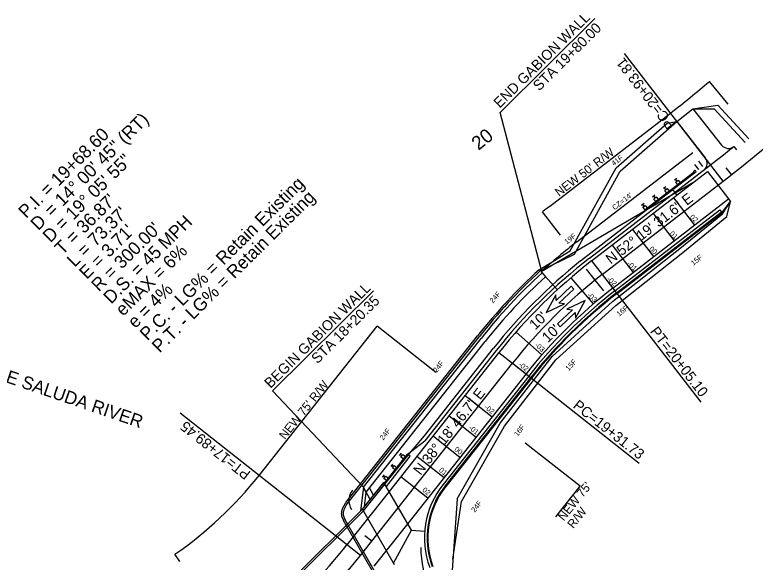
# Model space of a CAD drawing. Extents: x 126 to 1541327, y 13613 to 1200627.
# Drawn here: x 1539946.5 to 1540376.1, y 1199486.8 to 1199804.6 of the extents above; entities that cross this region are included whole.
import ezdxf

# ---------------------------------------------------------------- set-up
doc = ezdxf.new("R2010")
doc.units = 0
for name, color, linetype in [('BR_CONCRETE', 7, 'Continuous'), ('BR_PROPOSED_TRAVELWAY', 7, 'Continuous'), ('RD_HC_Cl', 7, 'Continuous'), ('RD_HC_Data', 7, 'Continuous'), ('RD_HC_Data_Tic', 7, 'Continuous'), ('RD_HC_TX_Sta50', 7, 'Continuous'), ('RD_PD_ALT1_TX', 7, 'Continuous'), ('RD_PD_BOC', 7, 'Continuous'), ('RD_PD_CstnLmt', 7, 'Continuous'), ('RD_PD_CstnLmt_TX', 7, 'Continuous'), ('RD_PD_DR_ErosCtrl', 7, 'Continuous'), ('RD_PD_Driveway', 7, 'Continuous'), ('RD_PD_EOP', 7, 'Continuous'), ('RD_PD_Final_TrvlWay', 7, 'Continuous'), ('RD_PD_Final_TX', 7, 'Continuous'), ('RD_PD_FOC', 7, 'Continuous'), ('RD_PD_GR', 7, 'Continuous'), ('RD_PD_PaveShd', 7, 'Continuous'), ('RD_PD_RW', 7, 'Continuous'), ('RD_PD_WallFill', 7, 'Continuous'), ('RD_Sketch1', 7, 'Continuous'), ('RD_Sketch8', 7, 'Continuous')]:
    doc.layers.add(name, color=color, linetype=linetype)

# ---------------------------------------------------------------- blocks, each defined once
blk = doc.blocks.new('Guardrail_MTBBC2_Transition')
at = {"layer": 'RD_PD_GR'}
for p, q in [((0, 0.5), (0, 0)), ((21.25, 0.5), (0, 0.5)), ((0, 0), (21.25, 0)), ((3.875, 3.75), (2.125, 3.75)), ((2.125, 0.5), (2.125, 2.5)), ((2.125, 2.5), (3.875, 2.5)), ((3.875, 0.5), (2.125, 0.5)), ((3, 2.5), (3, 3.75)), ((3.875, 2.5), (3.875, 0.5)), ((11.875, 3.75), (10.125, 3.75)), ((10.125, 0.5), (10.125, 2.5)), ((10.125, 2.5), (11.875, 2.5)), ((11.875, 0.5), (10.125, 0.5)), ((11, 2.5), (11, 3.75)), ((11.875, 2.5), (11.875, 0.5)), ((15, 0.5), (15, 0)), ((19.875, 3.75), (18.125, 3.75)), ((18.125, 0.5), (18.125, 2.5)), ((18.125, 2.5), (19.875, 2.5)), ((19.875, 0.5), (18.125, 0.5)), ((19, 2.5), (19, 3.75)), ((19.875, 2.5), (19.875, 0.5)), ((21.25, 0), (21.25, 0.5))]:
    blk.add_line(p, q, dxfattribs=at)
blk = doc.blocks.new('Guardrail_MT2_Leading_with_Buffer')
at = {"layer": 'RD_PD_GR'}
for p, q in [((17.52, 4.7), (15.77, 4.61)), ((16.72, 3.41), (16.65, 4.66)), ((25.51, 5.13), (23.76, 5.04)), ((24.7, 3.84), (24.64, 5.09)), ((38.94, 2.11), (38.74, 5.85)), ((41.94, 2.27), (41.74, 6.01)), ((1.55, 3.84), (-0.2, 3.74)), ((-0.13, 2.5), (1.61, 2.59)), ((-0.03, 0.5), (-0.13, 2.5)), ((35.92, 2.44), (-0.03, 0.5)), ((1.72, 0.59), (-0.03, 0.5)), ((-0.03, 0.5), (0, 0)), ((0, 0), (36.95, 2)), ((0.74, 2.54), (0.67, 3.79)), ((1.61, 2.59), (1.72, 0.59)), ((9.53, 4.27), (7.79, 4.18)), ((7.85, 2.93), (9.6, 3.02)), ((7.96, 0.93), (7.85, 2.93)), ((9.71, 1.03), (7.96, 0.93)), ((8.73, 2.98), (8.66, 4.22)), ((9.6, 3.02), (9.71, 1.03)), ((15.84, 3.36), (17.59, 3.45)), ((15.95, 1.36), (15.84, 3.36)), ((17.7, 1.46), (15.95, 1.36)), ((17.59, 3.45), (17.7, 1.46)), ((20.17, -2.67), (19.97, 1.08)), ((23.83, 3.79), (25.58, 3.89)), ((23.94, 1.79), (23.83, 3.79)), ((25.69, 1.89), (23.94, 1.79)), ((25.58, 3.89), (25.69, 1.89)), ((32.43, 2.25), (32.45, 1.75)), ((36.89, 3), (35.89, 2.94)), ((35.89, 2.94), (35.92, 2.44)), ((36.95, 2), (36.89, 3))]:
    blk.add_line(p, q, dxfattribs=at)

msp = doc.modelspace()

# ---------------------------------------------------------------- linework, layer by layer
at = {"layer": 'BR_CONCRETE'}
for p, q in [((1540148.8, 1199530.38), (1540147.11, 1199516.61)), ((1540148.21, 1199517.71), (1540160.73, 1199533.19)), ((1540148.25, 1199517.64), (1540160.77, 1199533.12)), ((1540148.77, 1199516.74), (1540160.63, 1199531.35)), ((1540150.28, 1199527.59), (1540148.8, 1199530.38)), ((1540160.63, 1199531.35), (1540161.17, 1199532.42)), ((1540176.63, 1199505.52), (1540160.73, 1199533.19)), ((1540150.28, 1199527.59), (1540149.22, 1199518.96)), ((1540077.64, 1199447.44), (1540148.21, 1199517.71)), ((1540077.68, 1199447.36), (1540148.25, 1199517.64)), ((1540078.2, 1199446.47), (1540148.77, 1199516.74)), ((1540166.77, 1199485.39), (1540148.21, 1199517.71)), ((1540166.22, 1199486.37), (1540176.63, 1199505.52))]:
    msp.add_line(p, q, dxfattribs=at)
at = {"layer": 'BR_PROPOSED_TRAVELWAY'}
for p, q in [((1540163.75, 1199527.93), (1540139.23, 1199496.89)), ((1540174.48, 1199509.25), (1540154.92, 1199484.5))]:
    msp.add_line(p, q, dxfattribs=at)
msp.add_arc((1539911.68, 1199676.68), 290, 301.8034, 321.687, dxfattribs=at)
at = {"layer": 'RD_HC_Cl'}
for p, q in [((1540287.32, 1199653.79), (1540357.53, 1199708.01)), ((1540147.08, 1199490.69), (1540235.28, 1199602.33))]:
    msp.add_line(p, q, dxfattribs=at)
for centre, radius, start, end in [((1539929.71, 1200262.06), 700, 307.67455, 318.32753), ((1540470.67, 1199416.35), 300, 127.6745, 141.687), ((1539911.68, 1199676.68), 300, 272.8619, 321.687)]:
    msp.add_arc(centre, radius, start, end, dxfattribs=at)
at = {"layer": 'RD_HC_Data'}
for p, q in [((1540357.53, 1199708.01), (1540300.32, 1199782.11)), ((1540287.32, 1199653.79), (1540344.54, 1199579.69)), ((1540235.28, 1199602.33), (1540308.74, 1199544.29)), ((1540147.08, 1199490.69), (1540042.49, 1199573.33))]:
    msp.add_line(p, q, dxfattribs=at)
at = {"layer": 'RD_HC_Data_Tic'}
for p, q in [((1540362.42, 1199711.82), (1540359.33, 1199715.75)), ((1540283.31, 1199650.65), (1540278.32, 1199656.89)), ((1540288.31, 1199644.4), (1540283.31, 1199650.65)), ((1540215.61, 1199577.44), (1540211.69, 1199580.54)), ((1540153.62, 1199498.98), (1540149.69, 1199502.08))]:
    msp.add_line(p, q, dxfattribs=at)
at = {"layer": 'RD_PD_ALT1_TX'}
for p, q in [((1540328.7, 1199698.38), (1540340.92, 1199682.55)), ((1540316.83, 1199689.21), (1540329.05, 1199673.38)), ((1540304.95, 1199680.05), (1540317.18, 1199664.22)), ((1540293.08, 1199670.88), (1540305.31, 1199655.05)), ((1540281.21, 1199661.71), (1540293.43, 1199645.88)), ((1540269.18, 1199651.93), (1540282.18, 1199636.73)), ((1540237.35, 1199620.45), (1540252.4, 1199607.28)), ((1540227.44, 1199608.53), (1540243.13, 1199596.13)), ((1540207.77, 1199583.64), (1540223.46, 1199571.24)), ((1540198.47, 1199571.87), (1540214.16, 1199559.47)), ((1540189.17, 1199560.1), (1540204.86, 1199547.7)), ((1540179.87, 1199548.33), (1540195.56, 1199535.93)), ((1540170.57, 1199536.56), (1540186.26, 1199524.16))]:
    msp.add_line(p, q, dxfattribs=at)
at = {"layer": 'RD_PD_BOC'}
for p, q in [((1540295.88, 1199642.71), (1540356.75, 1199689.72)), ((1540355.52, 1199691.3), (1540356.75, 1199689.72)), ((1540246.27, 1199593.65), (1540196.54, 1199530.72)), ((1540161.03, 1199532.67), (1540174.44, 1199549.64))]:
    msp.add_line(p, q, dxfattribs=at)
for centre, radius, start, end in [((1540470.67, 1199416.35), 286, 127.6745, 141.687), ((1540234.21, 1199500.96), 48, 141.687, 200.1561)]:
    msp.add_arc(centre, radius, start, end, dxfattribs=at)
at = {"layer": 'RD_PD_CstnLmt'}
for p, q in [((1540339.99, 1199750.04), (1540352.24, 1199750.03)), ((1540352.24, 1199750.03), (1540370.26, 1199730.47)), ((1540297.73, 1199713.78), (1540330.56, 1199742.62)), ((1540271.25, 1199665.73), (1540297.73, 1199713.78)), ((1540357.17, 1199689.15), (1540361.86, 1199696.19)), ((1540332.34, 1199668.96), (1540357.17, 1199689.15)), ((1540293.35, 1199638.1), (1540332.34, 1199668.96)), ((1540251.41, 1199655.9), (1540271.25, 1199665.73)), ((1540258.24, 1199606.31), (1540293.35, 1199638.1)), ((1540139.32, 1199520.8), (1540215.86, 1199617.68)), ((1540228.23, 1199567.47), (1540258.24, 1199606.31)), ((1540203.17, 1199523.55), (1540228.23, 1199567.47)), ((1540203.17, 1199523.55), (1540198.31, 1199453.66)), ((1540158.58, 1199475.93), (1540138.18, 1199511.5))]:
    msp.add_line(p, q, dxfattribs=at)
msp.add_arc((1540470.67, 1199416.35), 324.75, 132.4676, 141.687, dxfattribs=at)
msp.add_spline([(1540139.32, 1199520.8), (1540138.72, 1199519.85), (1540138.14, 1199518.8), (1540137.42, 1199517.27), (1540137.04, 1199515.8), (1540136.98, 1199514.76), (1540137.15, 1199513.68), (1540138.18, 1199511.5)], degree=3, dxfattribs=at)
at = {"layer": 'RD_PD_DR_ErosCtrl'}
for p, q in [((1540339.99, 1199750.04), (1540354.45, 1199752.06)), ((1540354.45, 1199752.06), (1540372.47, 1199732.51)), ((1540295.36, 1199715.69), (1540325.01, 1199741.74)), ((1540320.46, 1199739.93), (1540320.46, 1199739.93)), ((1540325.01, 1199741.74), (1540330.56, 1199742.62)), ((1540325.01, 1199741.74), (1540325.01, 1199741.74)), ((1540268.82, 1199667.55), (1540295.36, 1199715.69)), ((1540359.67, 1199687.49), (1540361.86, 1199696.19)), ((1540334.2, 1199666.61), (1540359.67, 1199687.49)), ((1540250.74, 1199656.64), (1540268.82, 1199667.55)), ((1540295.29, 1199635.81), (1540334.2, 1199666.61)), ((1540260.45, 1199604.26), (1540295.29, 1199635.81)), ((1540138.53, 1199521.42), (1540215.08, 1199618.3)), ((1540230.74, 1199565.8), (1540260.45, 1199604.26)), ((1540205.77, 1199522.06), (1540230.74, 1199565.8)), ((1540200.74, 1199488.6), (1540205.77, 1199522.06)), ((1540157.72, 1199475.43), (1540137.31, 1199511))]:
    msp.add_line(p, q, dxfattribs=at)
for centre, radius, start, end in [((1540470.67, 1199416.35), 325.75, 132.4676, 141.687), ((1540150.09, 1199522.59), 9.74, 141.434, 211.687)]:
    msp.add_arc(centre, radius, start, end, dxfattribs=at)
msp.add_open_spline([(1540138.49, 1199521.36), (1540138.36, 1199521.17), (1540138.24, 1199520.99), (1540138.07, 1199520.71), (1540138.01, 1199520.62), (1540137.93, 1199520.48), (1540137.9, 1199520.44), (1540137.87, 1199520.39), (1540137.87, 1199520.38), (1540137.86, 1199520.38), (1540137.86, 1199520.38), (1540137.86, 1199520.38), (1540137.86, 1199520.38), (1540137.86, 1199520.38), (1540137.86, 1199520.38), (1540137.86, 1199520.37), (1540137.85, 1199520.35), (1540137.83, 1199520.33), (1540137.81, 1199520.29), (1540137.8, 1199520.27), (1540137.72, 1199520.14), (1540137.67, 1199520.04), (1540137.56, 1199519.84), (1540137.5, 1199519.75), (1540137.4, 1199519.55), (1540137.35, 1199519.46), (1540137.29, 1199519.34), (1540137.28, 1199519.32), (1540137.26, 1199519.29), (1540137.26, 1199519.28), (1540137.25, 1199519.26), (1540137.25, 1199519.26), (1540137.25, 1199519.26), (1540137.25, 1199519.26), (1540137.25, 1199519.26), (1540137.25, 1199519.25), (1540137.24, 1199519.24), (1540137.21, 1199519.18), (1540137.18, 1199519.13), (1540137.05, 1199518.88), (1540136.96, 1199518.68), (1540136.77, 1199518.28), (1540136.68, 1199518.08), (1540136.57, 1199517.83), (1540136.55, 1199517.77), (1540136.52, 1199517.71), (1540136.51, 1199517.69), (1540136.51, 1199517.67), (1540136.5, 1199517.66), (1540136.5, 1199517.65), (1540136.5, 1199517.65), (1540136.5, 1199517.65), (1540136.5, 1199517.65), (1540136.5, 1199517.65), (1540136.5, 1199517.65), (1540136.48, 1199517.62), (1540136.47, 1199517.59), (1540136.41, 1199517.44), (1540136.37, 1199517.32), (1540136.29, 1199517.08), (1540136.26, 1199516.96), (1540136.2, 1199516.72), (1540136.17, 1199516.61), (1540136.12, 1199516.38), (1540136.1, 1199516.26), (1540136.07, 1199516.09), (1540136.06, 1199516.04), (1540136.05, 1199515.98), (1540136.05, 1199515.97), (1540136.05, 1199515.97), (1540136.05, 1199515.96), (1540136.05, 1199515.96), (1540136.05, 1199515.96), (1540136.05, 1199515.96), (1540136.05, 1199515.95), (1540136.04, 1199515.93), (1540136.04, 1199515.9), (1540136.03, 1199515.85), (1540136.03, 1199515.82), (1540136.01, 1199515.66), (1540136, 1199515.53), (1540135.98, 1199515.28), (1540135.98, 1199515.15), (1540135.98, 1199514.97), (1540135.98, 1199514.91), (1540135.98, 1199514.82), (1540135.98, 1199514.79), (1540135.98, 1199514.76), (1540135.98, 1199514.75), (1540135.98, 1199514.73), (1540135.98, 1199514.73), (1540135.98, 1199514.73), (1540135.98, 1199514.73), (1540135.98, 1199514.72), (1540135.98, 1199514.72), (1540135.98, 1199514.71), (1540135.98, 1199514.69), (1540135.99, 1199514.62), (1540135.99, 1199514.56), (1540136, 1199514.44), (1540136, 1199514.38), (1540136.01, 1199514.26), (1540136.02, 1199514.19), (1540136.03, 1199514.06), (1540136.04, 1199513.99), (1540136.07, 1199513.85), (1540136.08, 1199513.78), (1540136.12, 1199513.64), (1540136.13, 1199513.56), (1540136.17, 1199513.45), (1540136.18, 1199513.42), (1540136.2, 1199513.37), (1540136.2, 1199513.36), (1540136.2, 1199513.35), (1540136.21, 1199513.34), (1540136.21, 1199513.34), (1540136.21, 1199513.34), (1540136.21, 1199513.34), (1540136.21, 1199513.34), (1540136.21, 1199513.34), (1540136.21, 1199513.34), (1540136.21, 1199513.34), (1540136.21, 1199513.32), (1540136.24, 1199513.25), (1540136.27, 1199513.18), (1540136.33, 1199513.01), (1540136.37, 1199512.91), (1540136.5, 1199512.59), (1540136.59, 1199512.38), (1540136.79, 1199511.97), (1540136.89, 1199511.77), (1540137.1, 1199511.37), (1540137.21, 1199511.18), (1540137.32, 1199510.99)], degree=3, dxfattribs=at)
at = {"layer": 'RD_PD_Driveway'}
for p, q in [((1540330.56, 1199742.62), (1540339.99, 1199750.04)), ((1540339.99, 1199750.04), (1540356.57, 1199728.96)), ((1540330.56, 1199742.62), (1540347.15, 1199721.53))]:
    msp.add_line(p, q, dxfattribs=at)
for centre, start, end in [((1540360.5, 1199732.05), 218.1815, 309.1043), ((1540343.22, 1199718.44), 307.6745, 38.1815)]:
    msp.add_arc(centre, 5, start, end, dxfattribs=at)
at = {"layer": 'RD_PD_EOP'}
for p, q in [((1540294.66, 1199644.3), (1540355.52, 1199691.3)), ((1540244.7, 1199594.89), (1540194.97, 1199531.96)), ((1540162.1, 1199530.8), (1540176.01, 1199548.4)), ((1540176.01, 1199548.4), (1540174.44, 1199549.64))]:
    msp.add_line(p, q, dxfattribs=at)
for centre, radius, start, end in [((1540470.67, 1199416.35), 288, 127.6745, 141.687), ((1540234.21, 1199500.96), 50, 141.687, 200.1561)]:
    msp.add_arc(centre, radius, start, end, dxfattribs=at)
at = {"layer": 'RD_PD_Final_TrvlWay'}
for p, q in [((1540281.21, 1199661.71), (1540348.41, 1199713.6)), ((1540348.41, 1199713.6), (1540360.63, 1199697.77)), ((1540293.43, 1199645.88), (1540360.63, 1199697.77)), ((1540227.44, 1199608.53), (1540163.75, 1199527.93)), ((1540243.13, 1199596.13), (1540174.48, 1199509.25))]:
    msp.add_line(p, q, dxfattribs=at)
for radius in [310, 290]:
    msp.add_arc((1540470.67, 1199416.35), radius, 127.6745, 141.687, dxfattribs=at)
at = {"layer": 'RD_PD_Final_TX'}
for p, q in [((1540283.1, 1199802.46), (1540228.15, 1199747.97)), ((1540252.42, 1199654.79), (1540228.15, 1199747.97)), ((1540269.35, 1199647.06), (1540260.63, 1199638.81)), ((1540262.17, 1199637.18), (1540270.89, 1199645.42)), ((1540270.89, 1199645.42), (1540269.35, 1199647.06)), ((1540154.64, 1199644.29), (1540096.11, 1199586.24)), ((1540260.4, 1199642.11), (1540254.75, 1199631.71)), ((1540260.63, 1199638.81), (1540260.4, 1199642.11)), ((1540254.75, 1199631.71), (1540265.45, 1199636.77)), ((1540265.45, 1199636.77), (1540262.17, 1199637.18)), ((1540277.49, 1199638.84), (1540266.8, 1199633.78)), ((1540271.85, 1199628.44), (1540277.49, 1199638.84)), ((1540270.07, 1199633.37), (1540261.36, 1199625.13)), ((1540266.8, 1199633.78), (1540270.07, 1199633.37)), ((1540262.9, 1199623.49), (1540271.62, 1199631.74)), ((1540271.62, 1199631.74), (1540271.85, 1199628.44)), ((1540261.36, 1199625.13), (1540262.9, 1199623.49)), ((1540148.8, 1199530.38), (1540096.11, 1199586.24))]:
    msp.add_line(p, q, dxfattribs=at)
at = {"layer": 'RD_PD_FOC'}
for p, q in [((1540295.57, 1199643.11), (1540356.44, 1199690.11)), ((1540196.15, 1199531.03), (1540245.88, 1199593.96)), ((1540161.3, 1199532.2), (1540174.83, 1199549.33))]:
    msp.add_line(p, q, dxfattribs=at)
for centre, radius, start, end in [((1540470.67, 1199416.35), 286.5, 127.6745, 141.687), ((1540234.21, 1199500.96), 48.5, 141.687, 200.1561)]:
    msp.add_arc(centre, radius, start, end, dxfattribs=at)
at = {"layer": 'RD_PD_GR'}
for p, q in [((1540337.92, 1199711.19), (1540338.23, 1199710.79)), ((1540274.75, 1199661.73), (1540312.5, 1199690.93)), ((1540184.19, 1199560.25), (1540224.3, 1199611.01)), ((1540174.47, 1199548.87), (1540184.19, 1199560.25))]:
    msp.add_line(p, q, dxfattribs=at)
msp.add_arc((1540470.67, 1199416.35), 314, 128.605, 141.687, dxfattribs=at)
at = {"layer": 'RD_PD_PaveShd'}
for p, q in [((1540363.66, 1199728.17), (1540365.28, 1199726.18)), ((1540279.99, 1199663.29), (1540350.2, 1199717.51)), ((1540360.63, 1199697.77), (1540361.86, 1199696.19)), ((1540356.75, 1199689.72), (1540361.86, 1199696.19)), ((1540225.87, 1199609.77), (1540184.47, 1199557.38)), ((1540174.44, 1199549.64), (1540184.47, 1199557.38)), ((1540176.63, 1199505.52), (1540184.36, 1199504.9))]:
    msp.add_line(p, q, dxfattribs=at)
for centre, radius, start, end in [((1539929.71, 1200262.06), 688, 307.67455, 309.10435), ((1540470.67, 1199416.35), 312, 127.6745, 141.687)]:
    msp.add_arc(centre, radius, start, end, dxfattribs=at)
at = {"layer": 'RD_PD_RW'}
for p, q in [((1540360.48, 1199752.82), (1540349.5, 1199765.79)), ((1540256.76, 1199693.37), (1540326.98, 1199747.59)), ((1540263.09, 1199676.73), (1540252.7, 1199690.18)), ((1540088.23, 1199537.19), (1540156.77, 1199623.94)), ((1540190.81, 1199597.04), (1540156.77, 1199623.94)), ((1540274.46, 1199530.94), (1540242.72, 1199556.02)), ((1540260.37, 1199513.11), (1540274.46, 1199530.94)), ((1540042.34, 1199487.31), (1540039.46, 1199491.48))]:
    msp.add_line(p, q, dxfattribs=at)
for centre, radius, start, end in [((1539929.71, 1200262.06), 650, 307.67455, 310.22781), ((1540470.67, 1199416.35), 350, 127.6745, 128.52), ((1539911.68, 1199676.68), 225, 304.604, 321.687)]:
    msp.add_arc(centre, radius, start, end, dxfattribs=at)
at = {"layer": 'RD_PD_WallFill'}
for p, q in [((1540252.42, 1199654.79), (1540254.45, 1199652.58)), ((1540148.8, 1199530.38), (1540217.04, 1199616.75)), ((1540150.34, 1199527.49), (1540219.39, 1199614.89)), ((1540152.62, 1199523.17), (1540148.8, 1199530.38)), ((1540154.67, 1199525.71), (1540152.37, 1199530.06))]:
    msp.add_line(p, q, dxfattribs=at)
for radius in [323.25, 320.25]:
    msp.add_arc((1540470.67, 1199416.35), radius, 132.4676, 141.687, dxfattribs=at)
at = {"layer": 'RD_Sketch1'}
msp.add_arc((1540258.69, 1199497.05), 76.64, 181.1834, 200.1561, dxfattribs=at)
at = {"layer": 'RD_Sketch8'}
for p, q in [((1540272.65, 1199672.79), (1540339.85, 1199724.68)), ((1540339.83, 1199706.98), (1540251.92, 1199655.35)), ((1540251.92, 1199655.35), (1540261.37, 1199645.02))]:
    msp.add_line(p, q, dxfattribs=at)
msp.add_arc((1540470.67, 1199416.35), 324, 127.6745, 132.4676, dxfattribs=at)

# ---------------------------------------------------------------- block references
at = {"layer": 'RD_PD_GR', "rotation": 34.58007675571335}
msp.add_blockref('Guardrail_MT2_Leading_with_Buffer', (1540312.5, 1199690.93), dxfattribs=at)
at = {"layer": 'RD_PD_RW', "rotation": 51.687032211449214}
msp.add_blockref('Guardrail_MTBBC2_Transition', (1540161.3, 1199532.2), dxfattribs=at)

# ---------------------------------------------------------------- texts
at = {"layer": 'RD_HC_Data'}
for s, height, rotation, p in [('PC=20+93.81', 6, 127.6745, (1540330.08, 1199741.12)), ('    = 14%%d 00\' 45" (RT)', 7.5, 44.7604, (1539960.15, 1199679.01)), ('P.I. = 19+68.60', 7.5, 44.7604, (1539953.11, 1199686.11)), ('D = 19%%d 05\' 55"', 7.5, 44.7604, (1539967.19, 1199671.91)), ('P.C. - LG% = Retain Existing', 7.5, 44.7604, (1540023.53, 1199615.1)), ('P.T. - LG% = Retain Existing', 7.5, 44.7604, (1540030.57, 1199608)), ('N 52%%d 19\' 31.6" E', 6, 37.6745, (1540292.29, 1199659.54)), ("T = 36.87'", 7.5, 44.7604, (1539974.24, 1199664.8)), ("L = 73.37'", 7.5, 44.7604, (1539981.28, 1199657.7)), ('D.S. = 45 MPH', 7.5, 44.7604, (1540002.4, 1199636.4)), ('D', 7.5, 44.7604, (1539960.15, 1199679.01)), ("R = 300.00'", 7.5, 44.7604, (1539995.36, 1199643.5)), ("E = 3.71'", 7.5, 44.7604, (1539988.32, 1199650.6)), ('eMAX = 6%', 7.5, 44.7604, (1540009.44, 1199629.3)), ('e = 4%', 7.5, 44.7604, (1540016.48, 1199622.2)), ('PT=20+05.10', 6, 307.6745, (1540314.77, 1199620.69)), ('MIDDLE SALUDA RIVER', 7.5, 341.1022, (1539911.29, 1199601.54)), ('N 38%%d 18\' 46.7" E', 6, 51.687, (1540181.94, 1199536.95)), ('PC=19+31.73', 6, 321.687, (1540269.93, 1199576.86)), ('PT=17+89.45', 6, 141.687, (1540083.83, 1199539.01))]:
    msp.add_text(s, height=height, rotation=rotation, dxfattribs=at).set_placement(p)
at = {"layer": 'RD_HC_TX_Sta50'}
msp.add_text('20', height=8, rotation=38.5574, dxfattribs=at).set_placement((1540215.55, 1199725.59))
at = {"layer": 'RD_PD_ALT1_TX'}
for s, rotation, p in [('02', 318.3275, (1540337.87, 1199686.77)), ('01', 318.3275, (1540326.18, 1199677.15)), ('00', 318.3275, (1540314.26, 1199668.27)), ('-01', 318.3275, (1540301.5, 1199659.69)), ('-02', 318.3275, (1540289.73, 1199650.84)), ('-03', 318.3275, (1540278.28, 1199641.47)), ('-03', 318.8222, (1540247.91, 1199612.54)), ('-02', 321.687, (1540238.49, 1199601.07)), ('-02', 321.687, (1540218.7, 1199576.27)), ('-01', 321.687, (1540209.6, 1199564.35)), ('00', 321.687, (1540201.24, 1199551.83)), ('01', 321.687, (1540192.32, 1199539.77)), ('02', 321.687, (1540182.68, 1199528.26))]:
    msp.add_text(s, height=3, rotation=rotation, dxfattribs=at).set_placement(p)
at = {"layer": 'RD_PD_CstnLmt_TX'}
for s, rotation, p in [('41F', 37.6745, (1540294.08, 1199716.73)), ('19F', 38.6479, (1540266.88, 1199671.2)), ('15F', 37.6745, (1540340.16, 1199658.84)), ('24F', 48.1972, (1540223.93, 1199636.98)), ('16F', 38.6479, (1540297.14, 1199629.28)), ('24F', 51.687, (1540191.29, 1199596.66)), ('15F', 48.1972, (1540267.93, 1199597.64)), ('24F', 51.687, (1540160.29, 1199557.43)), ('16F', 51.687, (1540238.22, 1199559.58)), ('24F', 51.687, (1540213.37, 1199515.49))]:
    msp.add_text(s, height=3, rotation=rotation, dxfattribs=at).set_placement(p)
at = {"layer": 'RD_PD_Final_TX'}
for s, rotation, p in [('END GABION WALL', 44.7604, (1540227.92, 1199750.07)), ('STA 19+80.00', 44.7604, (1540250.77, 1199760.04)), ('BEGIN GABION WALL', 44.7604, (1540094.94, 1199587.41)), ('STA 18+20.35', 44.7604, (1540122.15, 1199601.71)), ("10'", 43.4043, (1540248.46, 1199621.38)), ("10'", 43.4043, (1540255.83, 1199613.98))]:
    msp.add_text(s, height=6, rotation=rotation, dxfattribs=at).set_placement(p)
at = {"layer": 'RD_PD_RW'}
for s, rotation, p in [("NEW 50' R/W", 37.6201, (1540262.33, 1199698.85)), ("NEW 75' R/W", 51.2447, (1540103.28, 1199557.7)), ("NEW 75' ", 51.2447, (1540265.09, 1199510.44)), ('R/W', 51.2447, (1540270.55, 1199506.06))]:
    msp.add_text(s, height=5, rotation=rotation, dxfattribs=at).set_placement(p)
at = {"layer": 'RD_Sketch8'}
msp.add_text("CZ=14'", height=3, rotation=37.6745, dxfattribs=at).set_placement((1540294.51, 1199691.08))

doc.saveas('drawing.dxf')
